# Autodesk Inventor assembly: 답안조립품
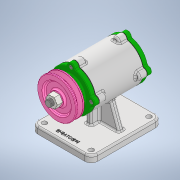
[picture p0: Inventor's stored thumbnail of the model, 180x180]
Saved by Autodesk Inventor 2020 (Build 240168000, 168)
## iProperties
Created: 2022-11
Part Number: 답안조립품
Document SubType Name: Assembly
Designer: owner
Author: owner
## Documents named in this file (12)
- C:\Users\owner\Desktop\721108V1019\답안조립품.iam
- C:\Users\owner\Desktop\721108V1019\본체.ipt
- C:\Users\owner\Desktop\721108V1019\V-벨트풀리.ipt
- C:\Users\owner\Desktop\721108V1019\개스킷.ipt
- C:\Users\owner\Desktop\721108V1019\너트 M12 x 1.25.ipt
- C:\Users\owner\Desktop\721108V1019\뒤커버.ipt
- C:\Users\owner\Desktop\721108V1019\베어링 6204.ipt
- C:\Users\owner\Desktop\721108V1019\볼트 M4 x 12.ipt
- C:\Users\owner\Desktop\721108V1019\앞커버.ipt
- C:\Users\owner\Desktop\721108V1019\오일 실.ipt
- C:\Users\owner\Desktop\721108V1019\축.ipt
- C:\Users\owner\Desktop\721108V1019\키 4 x 4.ipt
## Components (8 placed, 6 different names)
1. V-벨트풀리:1 — 각도:1
2. 개스킷:1
3. KS B 1012 클래스 1 일반 - 미터 M12x1.25:1 — 각도:1
4. KS B 2023 6204 - 20 x 47 x 14:1
5. KS B 2804 D D - 20 32 8:1
6. KS B 1311 (I) 4 x 4 x 12:1
7. KS B 2023 6204 - 20 x 47 x 14:2
8. 개스킷:2
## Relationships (1: Angle 1)
- 각도:1 [Angle]: V-벨트풀리:1 ↔ KS B 1012 클래스 1 일반 - 미터 M12x1.25:1
